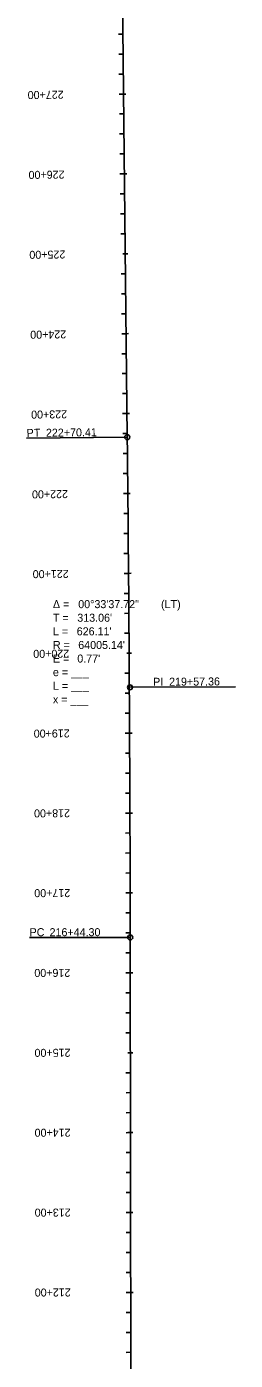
# Model space of a CAD drawing. Extents: x 23417911 to 23421158, y 6737892 to 6791804.
# Drawn here: x 23418167 to 23418428, y 6747590 to 6749259 of the extents above; entities that cross this region are included whole.
import ezdxf

# ---------------------------------------------------------------- set-up
doc = ezdxf.new("R2010")
doc.units = 0
for name, color, linetype in [('Alignment', 7, 'Continuous'), ('TextAlignment', 7, 'Continuous'), ('TextAlignmentLrg', 7, 'Continuous'), ('TextAlignmentSml', 7, 'Continuous')]:
    doc.layers.add(name, color=color, linetype=linetype)

msp = doc.modelspace()

# ---------------------------------------------------------------- linework, layer by layer
at = {"layer": 'Alignment'}
for p, q in [((23418292.6, 6748745.2), (23418260.7, 6751686.6)), ((23418292.6, 6748745.2), (23418260.7, 6751686.6)), ((23418298.6, 6745929.6), (23418296.3, 6748119.1)), ((23418298.6, 6745929.6), (23418296.3, 6748119.1))]:
    msp.add_line(p, q, dxfattribs=at)
msp.add_arc((23354291.2, 6748051.3), 64005.1, 0.060653, 0.621131, dxfattribs=at)
msp.add_arc((23354291.2, 6748051.3), 64005.1, 0.060653, 0.621131, dxfattribs=at)
at = {"layer": 'TextAlignment'}
for p, q in [((23418292.6, 6748745.2), (23418166.6, 6748743.8)), ((23418166.6, 6748743.8), (23418166.6, 6748743.8)), ((23418296, 6748432.1), (23418428, 6748432.9)), ((23418428, 6748432.9), (23418428, 6748432.9)), ((23418296.3, 6748119.1), (23418170.3, 6748118.9)), ((23418170.3, 6748118.9), (23418170.3, 6748118.9))]:
    msp.add_line(p, q, dxfattribs=at)
for centre in [(23418292.6, 6748745.2), (23418296, 6748432.1), (23418296.3, 6748119.1)]:
    msp.add_circle(centre, 3.12, dxfattribs=at)
at = {"layer": 'TextAlignmentLrg'}
for p, q in [((23418287.9, 6749174.7), (23418282.5, 6749174.7)), ((23418289, 6749074.7), (23418283.5, 6749074.7)), ((23418287, 6748974.7), (23418293.2, 6748974.8)), ((23418291.2, 6748874.7), (23418285.7, 6748874.7)), ((23418292.3, 6748774.7), (23418286.8, 6748774.7)), ((23418293.3, 6748674.7), (23418287.8, 6748674.7)), ((23418294.2, 6748574.7), (23418288.7, 6748574.7)), ((23418291.9, 6748474.7), (23418298, 6748474.8)), ((23418295.5, 6748374.8), (23418290.1, 6748374.7)), ((23418296, 6748274.8), (23418290.5, 6748274.7)), ((23418296.2, 6748174.8), (23418290.8, 6748174.7)), ((23418296.4, 6748074.8), (23418290.9, 6748074.7)), ((23418293.4, 6747974.8), (23418299.5, 6747974.8)), ((23418296.6, 6747874.8), (23418291.1, 6747874.7)), ((23418296.7, 6747774.8), (23418291.2, 6747774.7)), ((23418296.8, 6747674.8), (23418291.3, 6747674.7))]:
    msp.add_line(p, q, dxfattribs=at)
at = {"layer": 'TextAlignmentSml'}
for p, q in [((23418287.1, 6749249.7), (23418281.7, 6749249.7)), ((23418287.4, 6749224.7), (23418281.9, 6749224.7)), ((23418287.7, 6749199.7), (23418282.2, 6749199.7)), ((23418284.9, 6749174.7), (23418291, 6749174.7)), ((23418288.2, 6749149.7), (23418282.7, 6749149.7)), ((23418288.5, 6749124.7), (23418283, 6749124.7)), ((23418288.7, 6749099.7), (23418283.3, 6749099.7)), ((23418285.9, 6749074.7), (23418292.1, 6749074.8)), ((23418289.3, 6749049.7), (23418283.8, 6749049.7)), ((23418289.5, 6749024.7), (23418284.1, 6749024.7)), ((23418289.8, 6748999.7), (23418284.4, 6748999.7)), ((23418287, 6748974.7), (23418293.2, 6748974.8)), ((23418290.4, 6748949.7), (23418284.9, 6748949.7)), ((23418290.6, 6748924.7), (23418285.2, 6748924.7)), ((23418290.9, 6748899.7), (23418285.4, 6748899.7)), ((23418288.1, 6748874.7), (23418294.2, 6748874.8)), ((23418291.4, 6748849.7), (23418286, 6748849.7)), ((23418291.7, 6748824.7), (23418286.3, 6748824.7)), ((23418292, 6748799.7), (23418286.5, 6748799.7)), ((23418289.2, 6748774.7), (23418295.3, 6748774.8)), ((23418292.5, 6748749.7), (23418287.1, 6748749.7)), ((23418292.8, 6748724.7), (23418287.3, 6748724.7)), ((23418293.1, 6748699.7), (23418287.6, 6748699.7)), ((23418290.2, 6748674.7), (23418296.4, 6748674.8)), ((23418293.5, 6748649.7), (23418288.1, 6748649.7)), ((23418293.8, 6748624.7), (23418288.3, 6748624.7)), ((23418294, 6748599.7), (23418288.5, 6748599.7)), ((23418291.1, 6748574.7), (23418297.3, 6748574.8)), ((23418294.4, 6748549.7), (23418288.9, 6748549.7)), ((23418294.6, 6748524.8), (23418289.1, 6748524.7)), ((23418294.8, 6748499.8), (23418289.3, 6748499.7)), ((23418291.9, 6748474.7), (23418298, 6748474.8)), ((23418295.1, 6748449.8), (23418289.6, 6748449.7)), ((23418295.3, 6748424.8), (23418289.8, 6748424.7)), ((23418295.4, 6748399.8), (23418289.9, 6748399.7)), ((23418292.5, 6748374.7), (23418298.6, 6748374.8)), ((23418295.6, 6748349.8), (23418290.2, 6748349.7)), ((23418295.8, 6748324.8), (23418290.3, 6748324.7)), ((23418295.9, 6748299.8), (23418290.4, 6748299.7)), ((23418292.9, 6748274.7), (23418299, 6748274.8)), ((23418296, 6748249.8), (23418290.6, 6748249.7)), ((23418296.1, 6748224.8), (23418290.6, 6748224.7)), ((23418296.2, 6748199.8), (23418290.7, 6748199.7)), ((23418293.2, 6748174.7), (23418299.3, 6748174.8)), ((23418296.3, 6748149.8), (23418290.8, 6748149.7)), ((23418296.3, 6748124.8), (23418290.8, 6748124.7)), ((23418296.3, 6748099.8), (23418290.9, 6748099.7)), ((23418293.3, 6748074.8), (23418299.4, 6748074.8)), ((23418296.4, 6748049.8), (23418290.9, 6748049.7)), ((23418296.4, 6748024.8), (23418290.9, 6748024.7)), ((23418296.4, 6747999.8), (23418291, 6747999.7)), ((23418293.4, 6747974.8), (23418299.5, 6747974.8)), ((23418296.5, 6747949.8), (23418291, 6747949.7)), ((23418296.5, 6747924.8), (23418291.1, 6747924.7)), ((23418296.5, 6747899.8), (23418291.1, 6747899.7)), ((23418293.5, 6747874.8), (23418299.6, 6747874.8)), ((23418296.6, 6747849.8), (23418291.1, 6747849.7)), ((23418296.6, 6747824.8), (23418291.2, 6747824.7)), ((23418296.6, 6747799.8), (23418291.2, 6747799.7)), ((23418293.6, 6747774.8), (23418299.7, 6747774.8)), ((23418296.7, 6747749.8), (23418291.2, 6747749.7)), ((23418296.7, 6747724.8), (23418291.3, 6747724.7)), ((23418296.7, 6747699.8), (23418291.3, 6747699.7)), ((23418293.7, 6747674.8), (23418299.8, 6747674.8)), ((23418296.8, 6747649.8), (23418291.3, 6747649.7)), ((23418296.8, 6747624.8), (23418291.4, 6747624.7)), ((23418296.9, 6747599.8), (23418291.4, 6747599.7))]:
    msp.add_line(p, q, dxfattribs=at)

# ---------------------------------------------------------------- texts
at = {"layer": 'TextAlignment'}
for s, rotation, p in [('PT', 0.6211, (23418166.6, 6748745.5)), ('222+70.41', 0.6211, (23418190.8, 6748745.7)), ('PI ', 0.3409, (23418325, 6748434)), ('219+57.36', 0.3409, (23418345, 6748434.1)), ('PC', 0.0607, (23418170.3, 6748120.6)), ('216+44.30', 0.0607, (23418195.3, 6748120.6))]:
    msp.add_text(s, height=10.02, rotation=rotation, dxfattribs=at).set_placement(p)
for s, p in [('Δ = ', (23418199.5, 6748531.2)), ('00°33\'37.72"', (23418231.2, 6748531.2)), (' (LT)', (23418331.2, 6748531.2)), ('T = ', (23418199.5, 6748514.2)), ("313.06'", (23418230, 6748514.2)), ('L = ', (23418199.5, 6748497.2)), ("626.11'", (23418229.3, 6748497.2)), ('R = ', (23418199.5, 6748480.1)), ("64005.14'", (23418231.2, 6748480.1)), ('E = ', (23418199.5, 6748463.1)), ("0.77'", (23418230, 6748463.1)), ('e = ___ ', (23418199.5, 6748446.1)), ('L = ___', (23418199.5, 6748429)), ('x = ___', (23418199.5, 6748412))]:
    msp.add_text(s, height=10.02, dxfattribs=at).set_placement(p)
at = {"layer": 'TextAlignmentLrg'}
for s, rotation, p in [('225+00', 180.6211, (23418215, 6748978.9)), ('220+00', 180.3791, (23418219.9, 6748479.3)), ('215+00', 180.0607, (23418221.5, 6747979.7))]:
    msp.add_text(s, height=10.02, rotation=rotation, dxfattribs=at).set_placement(p)
at = {"layer": 'TextAlignmentSml'}
for s, rotation, p in [('227+00', 180.6211, (23418212.9, 6749178.9)), ('226+00', 180.6211, (23418214, 6749078.9)), ('225+00', 180.6211, (23418215, 6748978.9)), ('224+00', 180.6211, (23418216.1, 6748878.9)), ('223+00', 180.6211, (23418217.2, 6748778.9)), ('222+00', 180.5581, (23418218.3, 6748679)), ('221+00', 180.4686, (23418219.2, 6748579.1)), ('220+00', 180.3791, (23418219.9, 6748479.3)), ('219+00', 180.2895, (23418220.5, 6748379.4)), ('218+00', 180.2, (23418220.9, 6748279.5)), ('217+00', 180.1105, (23418221.2, 6748179.6)), ('216+00', 180.0607, (23418221.3, 6748079.7)), ('215+00', 180.0607, (23418221.5, 6747979.7)), ('214+00', 180.0607, (23418221.6, 6747879.7)), ('213+00', 180.0607, (23418221.7, 6747779.7)), ('212+00', 180.0607, (23418221.8, 6747679.7))]:
    msp.add_text(s, height=10.02, rotation=rotation, dxfattribs=at).set_placement(p)

doc.saveas('drawing.dxf')
